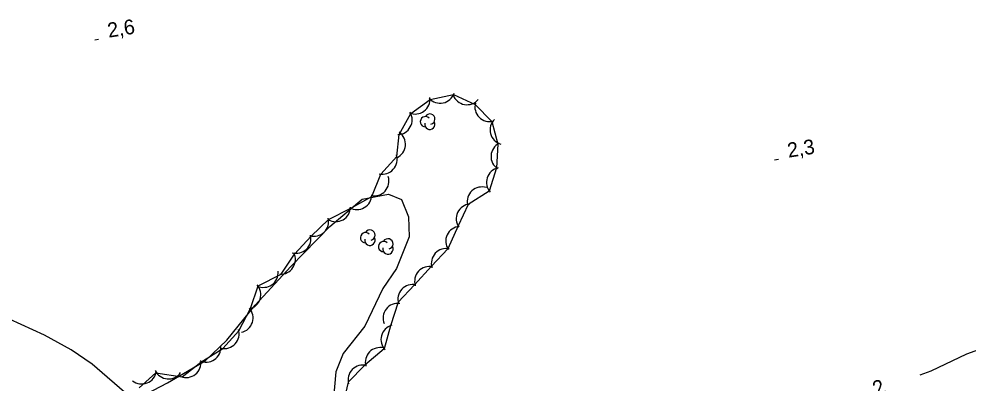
# Model space of a CAD drawing. Extents: x 643342 to 646936, y 5873857 to 5876103.
# Drawn here: x 644937.3 to 645130.8, y 5874834.4 to 5874908.6 of the extents above; entities that cross this region are included whole.
import ezdxf

# ---------------------------------------------------------------- set-up
doc = ezdxf.new("R2010")
doc.units = 0
for name, color, linetype in [('Niveau 2', 7, 'Continuous'), ('Niveau 22', 7, 'Continuous'), ('Niveau 3', 7, 'Continuous'), ('Niveau 44', 7, 'Continuous')]:
    doc.layers.add(name, color=color, linetype=linetype)

msp = doc.modelspace()

# ---------------------------------------------------------------- linework, layer by layer
at = {"layer": 'Niveau 2'}
for points in [[(644960.39, 5874830.9), (644967.52, 5874834.58), (644975.21, 5874839.08), (644979.65, 5874843.31), (644985.4, 5874850.4), (644992.7, 5874858.29), (645000.62, 5874866.42), (645007.19, 5874871.98), (645012.57, 5874872.98), (645015.2, 5874871.89), (645016.62, 5874868.41), (645016.79, 5874864.3), (645014.21, 5874857.88), (645011.42, 5874853.77), (645007.74, 5874846.15), (645003.33, 5874840.56), (645001.87, 5874836.83), (645001.28, 5874830.72)], [(645120.89, 5874836.24), (645123.08, 5874837.07), (645130.35, 5874840.5), (645136, 5874842.53)]]:
    msp.add_lwpolyline(points, dxfattribs=at)
at = {"layer": 'Niveau 22'}
msp.add_lwpolyline([(645021.76, 5874809.29), (645019.23, 5874809.08), (645016.78, 5874809.08), (645008.64, 5874811.55), (645004.24, 5874812.67), (645001.37, 5874813.02), (644997.97, 5874813.92), (644995.51, 5874815.19), (644992.13, 5874816.97), (644986.64, 5874819.47), (644982.57, 5874821.39), (644980.56, 5874822.01), (644976.98, 5874822.7), (644973.08, 5874823.02), (644971.11, 5874823.69), (644968.75, 5874825.11), (644963.51, 5874828.7), (644959.83, 5874831.79), (644952.18, 5874838.39), (644947.93, 5874841.3), (644942.5, 5874844.31), (644935.38, 5874847.59)], dxfattribs=at)
at = {"layer": 'Niveau 3'}
for p, q in [((644952.72, 5874904.43), (644953.51, 5874904.56)), ((645091.2, 5874880.01), (645091.99, 5874880.14))]:
    msp.add_line(p, q, dxfattribs=at)
at = {"layer": 'Niveau 44'}
msp.add_lwpolyline([(644961.8, 5874833.61), (644965.21, 5874836.62), (644970.56, 5874835.8), (644974.37, 5874838.81), (644978.79, 5874841.6), (644982.09, 5874845.16), (644984.47, 5874849.72), (644985.99, 5874854.33), (644990.72, 5874856.72), (644993.41, 5874860.76), (644996.85, 5874864.48), (645000.35, 5874867.84), (645004.92, 5874870.14), (645009.14, 5874872.54), (645011, 5874877.09), (645014.26, 5874880.69), (645014.76, 5874885.15), (645017.11, 5874889.4), (645021.06, 5874892.28), (645025.81, 5874893.28), (645030.2, 5874891.25), (645033.61, 5874887.8), (645034.85, 5874883.19), (645034.54, 5874878.35), (645033.1, 5874873.63), (645028.8, 5874870.92), (645026.73, 5874866.53), (645024.65, 5874861.9), (645021.35, 5874858.34), (645017.84, 5874854.57), (645014.54, 5874851.02), (645012.95, 5874846.22), (645011.69, 5874841.53), (645007.78, 5874838.18), (645004.38, 5874834.71), (645003.14, 5874829.5)], dxfattribs=at)
for centre, radius, start, end in [((645018, 5874892.3), 3, 246.8193, 6.7973), ((645018, 5874892.3), 3, 246.8193, 6.7973), ((645018, 5874892.3), 3, 246.8193, 6.7973), ((645023.08, 5874894.51), 3, 221.825, 341.803), ((645023.08, 5874894.51), 3, 221.825, 341.803), ((645023.08, 5874894.51), 3, 221.825, 341.803), ((645028.56, 5874894.21), 3, 199.8912, 319.8692), ((645028.56, 5874894.21), 3, 199.8912, 319.8692), ((645028.56, 5874894.21), 3, 199.8912, 319.8692), ((645033.16, 5874890.76), 3, 164.6436, 284.6215), ((645033.16, 5874890.76), 3, 164.6436, 284.6215), ((645033.16, 5874890.76), 3, 164.6436, 284.6215), ((645014.39, 5874888.13), 3, 271.0319, 31.0098), ((645014.39, 5874888.13), 3, 271.0319, 31.0098), ((645014.39, 5874888.13), 3, 271.0319, 31.0098), ((645020.09, 5874887.74), 1.05, 44.1154, 269.804), ((645020.99, 5874888.27), 1.05, 282.2692, 149.7263), ((645020.99, 5874887.22), 1.05, 166.9369, 29.6212), ((645036.26, 5874886.07), 3, 134.3833, 254.3612), ((645036.26, 5874886.07), 3, 134.3833, 254.3612), ((645036.26, 5874886.07), 3, 134.3833, 254.3612), ((645013.01, 5874883.14), 3, 294.8431, 54.821), ((645013.01, 5874883.14), 3, 294.8431, 54.821), ((645013.01, 5874883.14), 3, 294.8431, 54.821), ((645036.45, 5874880.66), 3, 116.3524, 236.3303), ((645036.45, 5874880.66), 3, 116.3524, 236.3303), ((645036.45, 5874880.66), 3, 116.3524, 236.3303), ((645011.32, 5874880.07), 3, 257.8724, 17.8504), ((645011.32, 5874880.07), 3, 257.8724, 17.8504), ((645011.32, 5874880.07), 3, 257.8724, 17.8504), ((645035.52, 5874875.41), 3, 102.2614, 222.2393), ((645035.52, 5874875.41), 3, 102.2614, 222.2393), ((645035.52, 5874875.41), 3, 102.2614, 222.2393), ((645009.65, 5874875.65), 3, 257.8726, 17.8506), ((645009.65, 5874875.65), 3, 257.8726, 17.8506), ((645009.65, 5874875.65), 3, 257.8726, 17.8506), ((645006.16, 5874872.87), 3, 239.6066, 359.5845), ((645006.16, 5874872.87), 3, 239.6066, 359.5845), ((645006.16, 5874872.87), 3, 239.6066, 359.5845), ((645031.59, 5874871.47), 3, 72.2678, 192.2457), ((645031.59, 5874871.47), 3, 72.2678, 192.2457), ((645031.59, 5874871.47), 3, 72.2678, 192.2457), ((645029.36, 5874867.98), 3, 94.8506, 214.8286), ((645029.36, 5874867.98), 3, 94.8506, 214.8286), ((645029.36, 5874867.98), 3, 94.8506, 214.8286), ((645001.82, 5874870.4), 3, 239.6066, 359.5845), ((645001.82, 5874870.4), 3, 239.6066, 359.5845), ((645001.82, 5874870.4), 3, 239.6066, 359.5845), ((644997.38, 5874867.43), 3, 253.8897, 13.8676), ((644997.38, 5874867.43), 3, 253.8897, 13.8676), ((644997.38, 5874867.43), 3, 253.8897, 13.8676), ((645007.89, 5874864.14), 1.05, 44.1154, 269.804), ((645008.79, 5874864.67), 1.05, 282.2692, 149.7263), ((645027.23, 5874863.45), 3, 94.8506, 214.8286), ((645027.23, 5874863.45), 3, 94.8506, 214.8286), ((645027.23, 5874863.45), 3, 94.8506, 214.8286), ((644993.77, 5874863.97), 3, 253.8897, 13.8676), ((644993.77, 5874863.97), 3, 253.8897, 13.8676), ((644993.77, 5874863.97), 3, 253.8897, 13.8676), ((645008.79, 5874863.62), 1.05, 166.9369, 29.6212), ((645011.56, 5874862.35), 1.05, 44.1154, 269.804), ((645012.46, 5874862.88), 1.05, 282.2692, 149.7263), ((645012.46, 5874861.83), 1.05, 166.9369, 29.6212), ((645024.29, 5874858.92), 3, 77.1222, 197.1001), ((645024.29, 5874858.92), 3, 77.1222, 197.1001), ((645024.29, 5874858.92), 3, 77.1222, 197.1001), ((644990.6, 5874859.72), 3, 266.2925, 26.2705), ((644990.6, 5874859.72), 3, 266.2925, 26.2705), ((644990.6, 5874859.72), 3, 266.2925, 26.2705), ((645020.89, 5874855.26), 3, 77.1222, 197.1001), ((645020.89, 5874855.26), 3, 77.1222, 197.1001), ((645020.89, 5874855.26), 3, 77.1222, 197.1001), ((644987.1, 5874857.03), 3, 245.1969, 5.1749), ((644987.1, 5874857.03), 3, 245.1969, 5.1749), ((644987.1, 5874857.03), 3, 245.1969, 5.1749), ((644983.56, 5874852.58), 3, 281.7861, 41.764), ((644983.56, 5874852.58), 3, 281.7861, 41.764), ((644983.56, 5874852.58), 3, 281.7861, 41.764), ((645017.48, 5874851.6), 3, 77.1222, 197.1001), ((645017.48, 5874851.6), 3, 77.1222, 197.1001), ((645017.48, 5874851.6), 3, 77.1222, 197.1001), ((644981.99, 5874847.83), 3, 281.7861, 41.764), ((644981.99, 5874847.83), 3, 281.7861, 41.764), ((644981.99, 5874847.83), 3, 281.7861, 41.764), ((645014.46, 5874847.78), 3, 82.1435, 202.1214), ((645014.46, 5874847.78), 3, 82.1435, 202.1214), ((645014.46, 5874847.78), 3, 82.1435, 202.1214), ((645014.03, 5874843.42), 3, 104.9688, 224.9467), ((645014.03, 5874843.42), 3, 104.9688, 224.9467), ((645014.03, 5874843.42), 3, 104.9688, 224.9467), ((644979.14, 5874844.58), 3, 257.2017, 17.1796), ((644979.14, 5874844.58), 3, 257.2017, 17.1796), ((644979.14, 5874844.58), 3, 257.2017, 17.1796), ((644975.41, 5874841.81), 3, 244.3646, 4.3425), ((644975.41, 5874841.81), 3, 244.3646, 4.3425), ((644975.41, 5874841.81), 3, 244.3646, 4.3425), ((645010.84, 5874838.79), 3, 75.6747, 195.6527), ((645010.84, 5874838.79), 3, 75.6747, 195.6527), ((645010.84, 5874838.79), 3, 75.6747, 195.6527), ((644971.38, 5874838.69), 3, 248.2595, 8.2375), ((644971.38, 5874838.69), 3, 248.2595, 8.2375), ((644971.38, 5874838.69), 3, 248.2595, 8.2375), ((645007.34, 5874835.22), 3, 75.6747, 195.6527), ((645007.34, 5874835.22), 3, 75.6747, 195.6527), ((645007.34, 5874835.22), 3, 75.6747, 195.6527), ((644962.31, 5874837.37), 3, 231.5387, 351.5166), ((644962.31, 5874837.37), 3, 231.5387, 351.5166), ((644962.31, 5874837.37), 3, 231.5387, 351.5166), ((644967.77, 5874838.4), 3, 204.9751, 324.953), ((644967.77, 5874838.4), 3, 204.9751, 324.953), ((644967.77, 5874838.4), 3, 204.9751, 324.953)]:
    msp.add_arc(centre, radius, start, end, dxfattribs=at)

# ---------------------------------------------------------------- texts
at = {"layer": 'Niveau 2'}
msp.add_text('2', height=3, rotation=25.7543, dxfattribs=at).set_placement((645112.09, 5874831.87))
at = {"layer": 'Niveau 3'}
for s, p in [('2,6  ', (644955.57, 5874904.84)), ('2,3  ', (645094.05, 5874880.42))]:
    msp.add_text(s, height=3, rotation=8.941, dxfattribs=at).set_placement(p)

doc.saveas('drawing.dxf')
